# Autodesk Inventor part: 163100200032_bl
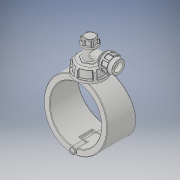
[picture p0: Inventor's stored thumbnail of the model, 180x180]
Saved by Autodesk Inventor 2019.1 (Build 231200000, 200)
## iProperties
Created: 2022-02
Part Number: 163100200032_bl
Material: Generic
Description: Plassadle Tapper 200x32
Document SubType Name: Modeling
Designer: comp2
Density: 1 g/cm^3
Appearance: Default
Author: comp2
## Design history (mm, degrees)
derived "16310.ipt"
feature "Solid1::16310.ipt" dims "ScaleForDerivedMember" = 10
feature "Solid2::16310.ipt" dims "ScaleForDerivedMember" = 10
feature "Solid3::16310.ipt" dims "ScaleForDerivedMember" = 10
feature "Solid4::16310.ipt" dims "ScaleForDerivedMember" = 10
tag "TaggingFeature1"
body "Solid1"
body "Solid2"
body "Solid3"
body "Solid4"
other parameters: "d2" = 246 [user parameter], "d5" = 368 [user parameter], "d7" = 233.7 [user parameter], "d8" = 85 deg [user parameter], "d9" = 45 deg [user parameter], "d10" = 115 [user parameter], "d11" = 49 [user parameter], "d12" = 34.3 [user parameter], "d13" = 40.25 [user parameter], "d14" = 62.1 [user parameter], "d15" = 2.45 [user parameter], "d16" = 2 [user parameter], "d17" = 2 [user parameter], "d18" = 29.4 [user parameter], "d19" = 7.35 [user parameter], "d20" = 1 [user parameter], "d21" = 34.5 [user parameter], "d22" = 1 [user parameter], "d23" = 14.7 [user parameter], "d24" = 111 [user parameter], "d27" = 144 [user parameter], "d29" = 64 [user parameter], "d31" = 51.2 [user parameter], "d32" = 44.4 [user parameter], "d33" = 15.54 [user parameter], "d34" = 93 deg [user parameter], "d35" = 2 [user parameter], "d36" = 4 [user parameter], "d39" = 45 deg [user parameter], "d40" = 4 [user parameter], "d41" = 5 [user parameter], "d42" = 4.6 [user parameter], "d46" = 57.5 [user parameter], "d47" = 32 [user parameter], "d48" = 49 [user parameter], "d49" = 4.92 [user parameter], "d50" = 144 [user parameter], "d51" = 0 [user parameter], "d52" = 32.2 [user parameter], "d53" = 135.3 [user parameter], "d54" = 50.4 [user parameter], "d55" = 0 [user parameter], "d56" = 28.8 [user parameter], "d57" = 28.8 [user parameter], "d59" = 0 [user parameter], "d60" = 144 [user parameter], "d61" = 0 [user parameter], "d62" = 50.4 [user parameter], "d63" = 0 [user parameter], "d65" = 0 [user parameter], "d67" = 0 [user parameter], "d69" = 0 [user parameter], "d70" = 1 [user parameter], "d71" = 138.24 [user parameter], "d72" = 0 [user parameter], "d73" = 2 [user parameter], "d77" = 32 [user parameter], "d78" = 97.75 [user parameter], "d79" = 5.75 [user parameter], "d80" = 60 deg [user parameter], "d81" = 5.75 [user parameter], "d84" = 0 [user parameter], "d85" = 1 [user parameter], "d87" = 360 deg [user parameter], "d90" = 0 [user parameter], "d91" = 1 [user parameter], "d93" = 60 deg [user parameter], "d94" = 3.45 [user parameter], "d95" = 3.45 [user parameter], "d97" = 0 [user parameter], "d98" = 0.5 [user parameter], "d100" = 360 deg [user parameter], "d102" = 2 [user parameter], "d105" = 0 [user parameter], "d106" = 45 deg [user parameter], "d107" = 3.2 [user parameter], "d108" = 3.2 [user parameter], "d109" = 2.95332 [user parameter], "d110" = -8 [user parameter], "d112" = 0 [user parameter], "d113" = 0.5 [user parameter], "d115" = 360 deg [user parameter], "d117" = 0.5 [user parameter], "d1" = 32 [user parameter], "B" = 246 [user parameter], "L" = 144 [user parameter], "E_" = 64 [user parameter], "E1" = 115 [user parameter], "H1" = 368 [user parameter], "H2" = 144 [user parameter], "H3" = 111 [user parameter], "H_costum" = 49 [user parameter]
